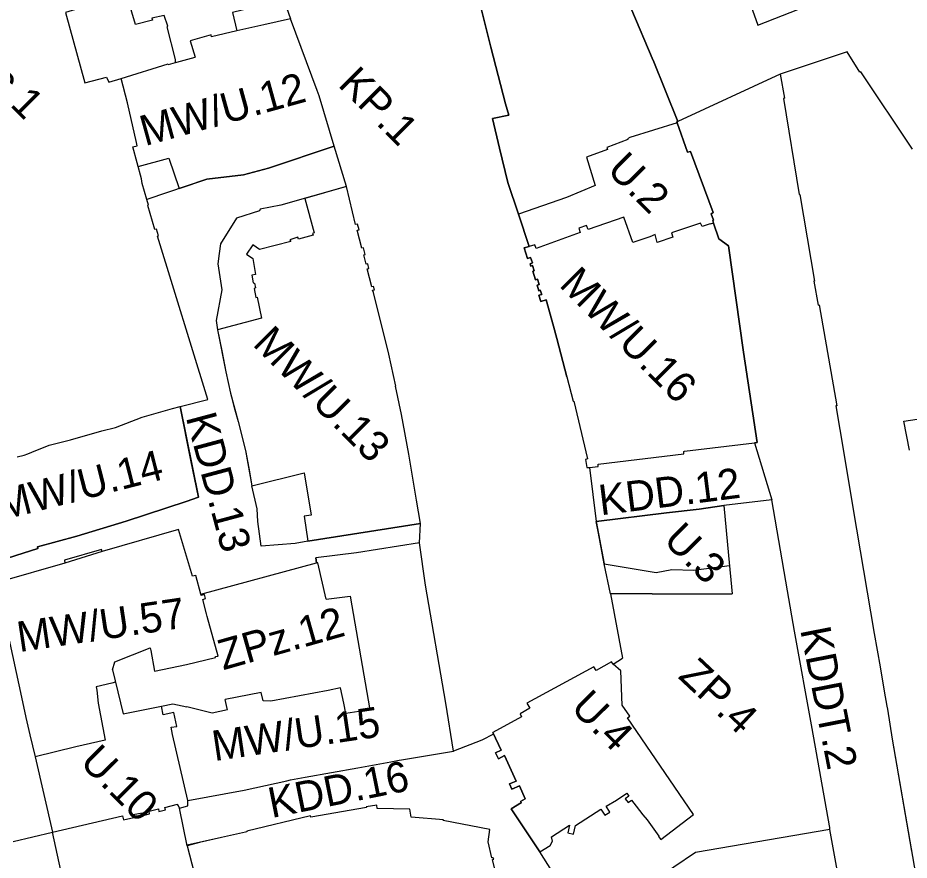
# Model space of a CAD drawing. Extents: x 7423835 to 7425280, y 5546086 to 5547600.
# Drawn here: x 7424593.5 to 7424769.7, y 5546646.4 to 5546812.9 of the extents above; entities that cross this region are included whole.
import ezdxf

# ---------------------------------------------------------------- set-up
doc = ezdxf.new("R2010")
doc.units = 0
for name, color, linetype in [('linie rozgraniczające', 7, 'Continuous'), ('nieprzekraczalne linie zabudowy', 7, 'Continuous'), ('obowiazujace linie zabudowy', 7, 'Continuous'), ('przeznaczenia terenów', 7, 'Continuous')]:
    doc.layers.add(name, color=color, linetype=linetype)

msp = doc.modelspace()

# ---------------------------------------------------------------- linework, layer by layer
at = {"layer": 'linie rozgraniczające'}
for p, q in [((7424744.2, 5546801.73), (7424723.96, 5546792.4)), ((7424658.44, 5546779.54), (7424656, 5546787.53)), ((7424739.1, 5546728.87), (7424742.53, 5546717.63)), ((7424706.52, 5546724.02), (7424707.81, 5546713.35)), ((7424673.09, 5546712.9), (7424650.85, 5546709.41)), ((7424672.9, 5546709.14), (7424673.09, 5546712.9)), ((7424710.67, 5546699.03), (7424713.01, 5546686.29)), ((7424718.86, 5546699.03), (7424734.7, 5546699.02)), ((7424711.18, 5546685.15), (7424713.01, 5546686.29)), ((7424626.99, 5546649.25), (7424625.45, 5546656.67)), ((7424696.68, 5546648.02), (7424691, 5546656.51)), ((7424592.61, 5546650.05), (7424600.35, 5546651.93)), ((7424600.28, 5546651.91), (7424602.25, 5546642.86)), ((7424758.3, 5546628.25), (7424754.02, 5546652.48)), ((7424706.02, 5546633.43), (7424696.68, 5546648.02))]:
    msp.add_line(p, q, dxfattribs=at)
for points in [[(7424707.32, 5546858.05), (7424711.92, 5546845.42), (7424716.09, 5546833.3), (7424721.67, 5546817.38), (7424714.67, 5546814.85), (7424719.05, 5546804.46), (7424719.1, 5546804.48), (7424723.96, 5546792.4), (7424723.75, 5546792.31), (7424723.82, 5546792.13), (7424725.89, 5546786.32), (7424726.44, 5546786.48), (7424730.93, 5546774.39), (7424730.57, 5546774.15), (7424730.99, 5546772.88), (7424730.86, 5546772.81), (7424730.99, 5546772.29), (7424732.04, 5546769.19), (7424733.94, 5546767.8), (7424736.9, 5546746.82), (7424739.64, 5546728.94), (7424739.1, 5546728.87)], [(7424751, 5546815.84), (7424727.03, 5546851.95), (7424725.66, 5546851.07), (7424739.75, 5546811.41), (7424751, 5546815.84)], [(7424643.66, 5546821.4), (7424646.21, 5546816.04), (7424647.41, 5546812.7)], [(7424702, 5546741.9), (7424700.04, 5546749.47), (7424699.37, 5546751.92), (7424697.94, 5546757.16), (7424696.87, 5546756.83), (7424696.49, 5546758.03), (7424697.06, 5546758.21), (7424696.74, 5546759.03), (7424696.48, 5546758.95), (7424696.14, 5546760.05), (7424696.54, 5546760.17), (7424696.22, 5546761.21), (7424695.8, 5546761.08), (7424695.27, 5546762.78), (7424695.58, 5546762.89), (7424695.23, 5546763.91), (7424694.91, 5546763.81), (7424694.75, 5546764.28), (7424695.2, 5546764.43), (7424694.83, 5546765.51), (7424694.26, 5546765.32), (7424693.6, 5546767.4), (7424694.54, 5546767.67), (7424692.46, 5546774.08), (7424690.38, 5546780.3), (7424688.7, 5546787.12), (7424687.32, 5546792.99), (7424690.57, 5546793.63), (7424689.87, 5546795.86), (7424686.98, 5546807.09), (7424683.36, 5546821.62)], [(7424647.41, 5546812.7), (7424647.41, 5546812.7), (7424642.11, 5546811.49), (7424636.8, 5546810.28), (7424631.79, 5546809.15), (7424631.69, 5546809.49), (7424627.56, 5546808.3), (7424628.58, 5546805.1)], [(7424656, 5546787.53), (7424653.03, 5546797.45), (7424652.66, 5546798.5), (7424647.41, 5546812.7)], [(7424770.35, 5546786.91), (7424760.14, 5546802.21), (7424759.95, 5546802.15), (7424757.39, 5546806.16), (7424744.2, 5546801.73), (7424745, 5546796.98), (7424744.83, 5546796.95), (7424747.95, 5546777.93), (7424748.07, 5546777.95), (7424750.99, 5546760.85), (7424750.82, 5546760.82), (7424751.7, 5546756.11), (7424751.86, 5546756.12), (7424755.35, 5546736.2), (7424755.21, 5546736.18), (7424756, 5546731.49), (7424759.29, 5546711.78), (7424762.74, 5546691.17), (7424763.95, 5546684.61), (7424764.73, 5546679.78), (7424765.23, 5546676.86), (7424765.39, 5546676.23), (7424766.34, 5546670.29), (7424771.49, 5546640.27)], [(7424613.91, 5546800.91), (7424623.22, 5546803.8), (7424623.27, 5546803.63), (7424624.67, 5546804.03), (7424624.91, 5546804.1), (7424628.58, 5546805.1)], [(7424625.59, 5546736.08), (7424631.08, 5546737.46), (7424621.12, 5546769.75), (7424621.3, 5546769.76), (7424620.9, 5546771.09), (7424620.56, 5546771.02), (7424619.19, 5546775.78), (7424619.31, 5546775.86), (7424618.99, 5546776.95), (7424618.07, 5546780.15), (7424617.92, 5546781.08), (7424616.24, 5546787.36), (7424617.08, 5546787.59), (7424616.94, 5546788.21), (7424615.16, 5546796.1), (7424613.91, 5546800.91), (7424613.91, 5546800.91)], [(7424723.82, 5546792.13), (7424714.48, 5546789.2)], [(7424714.48, 5546789.2), (7424714, 5546788.98), (7424714.05, 5546788.8), (7424709.93, 5546787.22), (7424710.05, 5546786.88), (7424705.87, 5546785.34), (7424707.63, 5546779.74), (7424701.94, 5546777.39), (7424692.46, 5546774.08)], [(7424656, 5546787.53), (7424643.06, 5546783.18), (7424638.14, 5546781.85), (7424630.83, 5546781), (7424618.99, 5546776.95)], [(7424658.44, 5546779.54), (7424645.46, 5546775.82), (7424641.39, 5546775.03), (7424641.24, 5546774.76), (7424636.75, 5546773.31), (7424633.58, 5546768.23), (7424633.3, 5546766.33), (7424633.01, 5546764.27), (7424633.81, 5546759.11), (7424632.73, 5546753.08), (7424632.99, 5546751.2), (7424634.64, 5546742.88), (7424635.52, 5546738.68), (7424637.05, 5546733.06), (7424638.51, 5546727.39), (7424639.78, 5546720.37)], [(7424673.09, 5546712.9), (7424672.33, 5546717.56), (7424670.76, 5546726.65), (7424669.36, 5546734.5), (7424668.12, 5546740.06), (7424668.22, 5546740.09), (7424666.82, 5546746.42), (7424663.77, 5546758.61), (7424663.63, 5546759.02), (7424664, 5546759.1), (7424663.83, 5546759.79), (7424663.47, 5546759.7), (7424662.54, 5546763.26), (7424662.88, 5546763.34), (7424662.65, 5546764.24), (7424662.33, 5546764.16), (7424661.88, 5546766.05), (7424662.16, 5546766.13), (7424661.81, 5546767.44), (7424661.52, 5546767.36), (7424660.55, 5546770.88), (7424660.94, 5546770.98), (7424660.65, 5546772.09), (7424660.23, 5546772.01), (7424658.44, 5546779.54)], [(7424730.99, 5546772.29), (7424730.36, 5546772.07), (7424730.33, 5546772.17), (7424728.77, 5546771.61), (7424728.45, 5546772.32), (7424722.68, 5546770.36), (7424722.93, 5546769.5), (7424719.89, 5546768.49), (7424719.47, 5546770.05), (7424718.41, 5546769.61), (7424715.03, 5546768.5), (7424713.25, 5546773.49), (7424706.2, 5546771.06), (7424705.91, 5546771.85), (7424704.4, 5546771.3), (7424704.64, 5546770.45), (7424695.95, 5546767.29), (7424695.69, 5546767.99), (7424694.54, 5546767.67)], [(7424702, 5546741.9), (7424703.25, 5546737.1), (7424703.4, 5546737.12), (7424706.11, 5546725.69), (7424705.67, 5546725.6), (7424705.99, 5546723.97), (7424706.52, 5546724.02), (7424708.21, 5546724.19), (7424708.18, 5546724.68), (7424725.16, 5546726.72), (7424725.11, 5546727.18), (7424725.25, 5546727.2), (7424739.1, 5546728.87)], [(7424593.38, 5546726.12), (7424594.73, 5546726.44), (7424595.51, 5546726.69), (7424596.28, 5546727.03), (7424599.71, 5546728.44), (7424603.9, 5546729.49), (7424610.1, 5546731.22), (7424612.8, 5546731.92), (7424618.1, 5546733.93), (7424618.56, 5546734.06), (7424624.08, 5546735.64), (7424625.59, 5546736.08), (7424629.2, 5546718.11), (7424626.77, 5546717.3), (7424614.94, 5546713.4), (7424605.17, 5546710.42), (7424597.4, 5546708.32), (7424597.47, 5546708.02), (7424588.52, 5546705.15)], [(7424769.71, 5546727.43), (7424768.63, 5546733.16), (7424772.59, 5546733.72)], [(7424650.85, 5546709.41), (7424648.29, 5546708.97), (7424641.62, 5546708.44), (7424640.96, 5546713.32), (7424640.8, 5546715.86), (7424639.78, 5546720.37)], [(7424707.81, 5546713.35), (7424721.68, 5546715.07), (7424728.18, 5546715.79), (7424733.05, 5546716.46)], [(7424754.02, 5546652.48), (7424753.96, 5546652.84), (7424753.9, 5546653.2), (7424750.47, 5546672.42), (7424747.04, 5546691.63), (7424745.65, 5546699.61), (7424742.53, 5546717.63), (7424733.05, 5546716.46)], [(7424733.05, 5546716.46), (7424733.97, 5546706.6), (7424734.7, 5546699.02)], [(7424718.86, 5546699.03), (7424710.67, 5546699.03), (7424709.38, 5546704.99), (7424708.25, 5546710.99), (7424707.81, 5546713.35)], [(7424629.67, 5546698.97), (7424628.68, 5546702.66), (7424628.03, 5546702.52), (7424625.27, 5546711.72), (7424610.16, 5546707.38), (7424610.03, 5546707.78), (7424602.7, 5546705.68), (7424602.82, 5546705.09), (7424602.82, 5546705.09)], [(7424591.23, 5546692.64), (7424594.43, 5546677.7), (7424595.11, 5546674.57), (7424595.9, 5546671.13), (7424596.9, 5546666.81), (7424600.35, 5546651.93), (7424614.17, 5546655.13), (7424614.38, 5546654.38), (7424616.4, 5546654.84), (7424616.27, 5546655.4), (7424618.1, 5546655.76), (7424618.23, 5546655.25), (7424619.56, 5546655.56), (7424619.43, 5546656.08), (7424621.28, 5546656.52), (7424621.4, 5546655.99), (7424622.7, 5546656.37), (7424622.59, 5546656.82), (7424625.04, 5546657.46), (7424625.07, 5546657.27), (7424625.12, 5546657.26), (7424625.45, 5546656.67), (7424627.08, 5546657.11), (7424627.12, 5546658.15), (7424638.25, 5546660.23), (7424646.64, 5546662.1), (7424647.37, 5546662.27), (7424650.31, 5546662.79), (7424660.7, 5546664.64), (7424667.21, 5546665.81), (7424668.9, 5546666.16), (7424669.35, 5546666.23), (7424674.48, 5546667.07), (7424679.61, 5546667.91), (7424678.08, 5546677.4), (7424674.08, 5546700.75), (7424672.9, 5546709.14), (7424660.46, 5546707.14), (7424652.38, 5546706.14)], [(7424629.67, 5546698.97), (7424652.55, 5546705.19), (7424652.38, 5546706.14)], [(7424602.82, 5546705.09), (7424589.91, 5546701.38)], [(7424654.45, 5546698), (7424652.83, 5546705.14), (7424652.55, 5546705.19)], [(7424633.09, 5546686.72), (7424630.95, 5546694.57), (7424630.82, 5546695.1), (7424630.1, 5546697.91), (7424630.6, 5546698.12), (7424630.37, 5546698.88), (7424629.73, 5546698.73), (7424629.67, 5546698.97)], [(7424654.45, 5546698), (7424659.17, 5546698.56), (7424663.07, 5546676.13)], [(7424612.19, 5546683.99), (7424612.67, 5546685.62), (7424619.65, 5546688.38)], [(7424619.65, 5546688.38), (7424619.76, 5546687.82), (7424620.54, 5546683.74), (7424626.84, 5546685.09), (7424632.58, 5546686.47), (7424632.55, 5546686.62), (7424633.09, 5546686.72)], [(7424712.71, 5546683.83), (7424711.18, 5546685.15), (7424710.87, 5546685.61), (7424707.82, 5546683.86), (7424707.38, 5546684.61), (7424694.13, 5546677.39), (7424694.7, 5546676.4), (7424692.79, 5546675.33), (7424693.04, 5546674.74), (7424687.39, 5546671.62)], [(7424612.19, 5546683.99), (7424614.35, 5546675.34), (7424621.92, 5546676.85), (7424624.16, 5546677.3), (7424626.91, 5546676.7)], [(7424696.68, 5546648.02), (7424698.72, 5546649.31), (7424699.18, 5546650.15), (7424698.98, 5546651.02), (7424702.54, 5546653.28), (7424702.24, 5546651.76), (7424703.35, 5546651.53), (7424703.71, 5546653.27), (7424708.75, 5546656.47), (7424709.5, 5546655.27), (7424710.5, 5546655.9), (7424709.76, 5546657.09), (7424711.81, 5546658.27), (7424713.89, 5546659.66), (7424714.28, 5546659.02), (7424713.57, 5546658.52), (7424714.15, 5546657.8), (7424714.8, 5546658.26), (7424715.73, 5546657.05), (7424717.03, 5546655.34), (7424717.89, 5546654.36), (7424720.21, 5546651.15), (7424720.16, 5546651.08), (7424720.58, 5546650.46), (7424727.03, 5546655.39), (7424713.97, 5546674.52), (7424714.49, 5546674.83), (7424712.94, 5546677.03), (7424712.71, 5546683.83)], [(7424612.79, 5546681.57), (7424612.11, 5546681.37), (7424608.99, 5546680.63), (7424609.11, 5546679.97), (7424609.35, 5546677.42), (7424610.77, 5546670.09), (7424604.95, 5546668.79), (7424596.9, 5546666.81)], [(7424663.07, 5546676.13), (7424662.64, 5546676.06), (7424658.36, 5546675.4), (7424657.97, 5546677.41), (7424657.29, 5546680.48), (7424654.84, 5546679.91), (7424643.53, 5546677.81), (7424642, 5546677.85), (7424641.58, 5546679.51), (7424634.5, 5546678.16)], [(7424634.94, 5546676.09), (7424634.89, 5546676.35), (7424634.5, 5546678.16)], [(7424627.12, 5546658.15), (7424624.07, 5546671.24), (7424623.81, 5546672.66), (7424624.93, 5546672.83), (7424624.37, 5546675.57), (7424622.25, 5546675.14), (7424621.92, 5546676.85)], [(7424634.94, 5546676.09), (7424631.89, 5546675.45), (7424626.91, 5546676.7)], [(7424687.54, 5546671.3), (7424685.18, 5546670.09), (7424679.61, 5546667.91)], [(7424691, 5546656.51), (7424693.02, 5546657.76), (7424692.88, 5546657.99), (7424693.79, 5546658.54), (7424692.63, 5546661.07), (7424691.13, 5546660.43), (7424690.67, 5546661.47), (7424692.01, 5546662.03), (7424689.67, 5546667.05), (7424688.48, 5546666.43), (7424687.94, 5546667.59), (7424689.02, 5546668.14), (7424687.39, 5546671.62)], [(7424689.87, 5546635.82), (7424687.29, 5546646.51), (7424687.56, 5546646.57), (7424687.47, 5546646.87), (7424687.22, 5546646.82), (7424686.45, 5546650.01), (7424686.77, 5546652.42), (7424677.6, 5546654.2), (7424677.63, 5546654.36), (7424671.22, 5546654.91), (7424670.97, 5546656.48), (7424664.53, 5546656.62), (7424664.44, 5546657.27), (7424662.37, 5546656.94), (7424662.39, 5546656.79), (7424651.42, 5546654.92), (7424651.33, 5546655.18), (7424638.75, 5546652.11), (7424638.77, 5546652.01), (7424638.51, 5546651.93), (7424633.79, 5546650.84), (7424629.42, 5546649.87), (7424626.99, 5546649.25), (7424631.53, 5546631.4)], [(7424754.02, 5546652.48), (7424727.46, 5546647.88), (7424706.02, 5546633.43)]]:
    msp.add_lwpolyline(points, dxfattribs=at)
at = {"layer": 'nieprzekraczalne linie zabudowy'}
msp.add_line((7424610.16, 5546707.38), (7424602.82, 5546705.09), dxfattribs=at)
for points in [[(7424617.27, 5546783.51), (7424623.35, 5546785.14), (7424625.41, 5546779.14)], [(7424722.79, 5546703.86), (7424727.07, 5546703.7), (7424734.16, 5546704.63)]]:
    msp.add_lwpolyline(points, dxfattribs=at)
at = {"layer": 'obowiazujace linie zabudowy'}
for p, q in [((7424658.44, 5546779.54), (7424650.21, 5546777.18)), ((7424627.73, 5546725.42), (7424625.59, 5546736.08)), ((7424650.85, 5546709.41), (7424673.09, 5546712.9)), ((7424691, 5546656.51), (7424696.68, 5546648.02))]:
    msp.add_line(p, q, dxfattribs=at)
for points in [[(7424739.1, 5546728.87), (7424739.64, 5546728.94), (7424736.9, 5546746.82), (7424733.94, 5546767.8), (7424732.04, 5546769.19), (7424730.99, 5546772.29), (7424730.86, 5546772.81), (7424730.99, 5546772.88), (7424730.57, 5546774.15), (7424730.93, 5546774.39), (7424726.44, 5546786.48), (7424725.89, 5546786.32), (7424723.82, 5546792.13), (7424723.75, 5546792.31), (7424723.96, 5546792.4), (7424719.1, 5546804.48), (7424719.05, 5546804.46), (7424714.67, 5546814.85), (7424721.67, 5546817.38), (7424716.09, 5546833.3), (7424711.92, 5546845.42), (7424707.32, 5546858.05)], [(7424617.07, 5546820.29), (7424614.34, 5546819.62), (7424606.95, 5546817.32), (7424607.56, 5546815.34), (7424602.92, 5546813.96), (7424606.74, 5546800), (7424611.02, 5546801.16), (7424611.48, 5546800.15), (7424613.91, 5546800.91)], [(7424624.67, 5546804.03), (7424624.69, 5546804.66), (7424623.01, 5546811.13), (7424623.17, 5546811.2), (7424622.42, 5546813.32), (7424619.96, 5546812.8), (7424620.09, 5546812.4), (7424616.79, 5546811.55), (7424615.3, 5546816.47), (7424617.95, 5546817.15), (7424617.07, 5546820.29)], [(7424683.36, 5546821.62), (7424686.98, 5546807.09), (7424689.87, 5546795.86), (7424690.57, 5546793.63), (7424687.32, 5546792.99), (7424688.7, 5546787.12), (7424690.38, 5546780.3), (7424692.46, 5546774.08), (7424694.54, 5546767.67), (7424693.6, 5546767.4), (7424694.26, 5546765.32), (7424694.83, 5546765.51), (7424695.2, 5546764.43), (7424694.75, 5546764.28), (7424694.91, 5546763.81), (7424695.23, 5546763.91), (7424695.58, 5546762.89), (7424695.27, 5546762.78), (7424695.8, 5546761.08), (7424696.22, 5546761.21), (7424696.54, 5546760.17), (7424696.14, 5546760.05), (7424696.48, 5546758.95), (7424696.74, 5546759.03), (7424697.06, 5546758.21), (7424696.49, 5546758.03), (7424696.87, 5546756.83), (7424697.94, 5546757.16), (7424699.37, 5546751.92), (7424700.04, 5546749.47), (7424702, 5546741.9)], [(7424646.04, 5546816.39), (7424635.93, 5546813.96), (7424636.8, 5546810.28)], [(7424656, 5546787.53), (7424653.03, 5546797.45), (7424652.66, 5546798.5), (7424647.41, 5546812.7)], [(7424770.35, 5546786.91), (7424760.14, 5546802.21), (7424759.95, 5546802.15), (7424757.39, 5546806.16), (7424744.2, 5546801.73), (7424745, 5546796.98), (7424744.83, 5546796.95), (7424747.95, 5546777.93), (7424748.07, 5546777.95), (7424750.99, 5546760.85), (7424750.82, 5546760.82), (7424751.7, 5546756.11), (7424751.86, 5546756.12), (7424755.35, 5546736.2), (7424755.21, 5546736.18), (7424756, 5546731.49), (7424759.29, 5546711.78), (7424762.74, 5546691.17), (7424763.95, 5546684.61), (7424764.73, 5546679.78), (7424765.23, 5546676.86), (7424765.39, 5546676.23), (7424766.34, 5546670.29), (7424770.14, 5546648.15)], [(7424625.41, 5546779.14), (7424630.83, 5546781), (7424638.14, 5546781.85), (7424643.06, 5546783.18), (7424656, 5546787.53)], [(7424673.09, 5546712.9), (7424672.33, 5546717.56), (7424670.76, 5546726.65), (7424669.36, 5546734.5), (7424668.12, 5546740.06), (7424668.22, 5546740.09), (7424666.82, 5546746.42), (7424663.77, 5546758.61), (7424663.63, 5546759.02), (7424664, 5546759.1), (7424663.83, 5546759.79), (7424663.47, 5546759.7), (7424662.54, 5546763.26), (7424662.88, 5546763.34), (7424662.65, 5546764.24), (7424662.33, 5546764.16), (7424661.88, 5546766.05), (7424662.16, 5546766.13), (7424661.81, 5546767.44), (7424661.52, 5546767.36), (7424660.55, 5546770.88), (7424660.94, 5546770.98), (7424660.65, 5546772.09), (7424660.23, 5546772.01), (7424658.44, 5546779.54)], [(7424650.21, 5546777.18), (7424652.06, 5546770.39), (7424651.77, 5546770.28), (7424651.88, 5546769.93), (7424648.95, 5546769.15), (7424648.83, 5546769.53), (7424647.29, 5546769.03), (7424647.43, 5546768.64), (7424641.25, 5546767.09), (7424639.95, 5546768.02), (7424638.71, 5546766.18), (7424639.96, 5546765.32), (7424640.48, 5546762.17), (7424639.73, 5546762.02), (7424640, 5546760.47), (7424640.28, 5546760.45), (7424640.47, 5546759.51), (7424640.2, 5546759.4), (7424640.53, 5546757.57), (7424640.83, 5546757.64), (7424641.69, 5546753.52), (7424632.99, 5546751.2)], [(7424632.99, 5546751.2), (7424633.82, 5546747.04), (7424634.64, 5546742.88), (7424635.52, 5546738.68), (7424636.29, 5546735.87), (7424637.05, 5546733.06), (7424637.78, 5546730.23), (7424638.51, 5546727.39), (7424639.15, 5546723.88), (7424639.78, 5546720.37)], [(7424702, 5546741.9), (7424703.25, 5546737.1), (7424703.4, 5546737.12), (7424706.11, 5546725.69), (7424705.67, 5546725.6), (7424705.99, 5546723.97), (7424706.52, 5546724.02), (7424708.21, 5546724.19), (7424708.18, 5546724.68), (7424725.16, 5546726.72), (7424725.11, 5546727.18), (7424725.25, 5546727.2), (7424739.1, 5546728.87)], [(7424626.77, 5546717.3), (7424629.2, 5546718.11), (7424627.73, 5546725.42)], [(7424583.6, 5546722.64), (7424584.37, 5546718.9), (7424588.52, 5546705.15), (7424597.47, 5546708.02), (7424597.4, 5546708.32), (7424605.17, 5546710.42), (7424614.94, 5546713.4), (7424626.77, 5546717.3)], [(7424639.78, 5546720.37), (7424650.08, 5546722.95), (7424651.5, 5546714.55), (7424650.12, 5546714.35), (7424650.85, 5546709.41)], [(7424733.05, 5546716.46), (7424728.18, 5546715.79), (7424721.68, 5546715.07), (7424707.81, 5546713.35), (7424709.38, 5546704.99)], [(7424629.67, 5546698.97), (7424628.68, 5546702.66), (7424628.03, 5546702.52), (7424625.27, 5546711.72), (7424610.16, 5546707.38)], [(7424591.23, 5546692.64), (7424594.43, 5546677.7), (7424595.11, 5546674.57), (7424595.9, 5546671.13), (7424596.9, 5546666.81), (7424600.35, 5546651.93), (7424614.17, 5546655.13), (7424614.38, 5546654.38), (7424616.4, 5546654.84), (7424616.27, 5546655.4), (7424618.1, 5546655.76), (7424618.23, 5546655.25), (7424619.56, 5546655.56), (7424619.43, 5546656.08), (7424621.28, 5546656.52), (7424621.4, 5546655.99), (7424622.7, 5546656.37), (7424622.59, 5546656.82), (7424625.04, 5546657.46), (7424625.07, 5546657.27), (7424625.12, 5546657.26), (7424625.45, 5546656.67), (7424627.08, 5546657.11), (7424627.12, 5546658.15), (7424638.25, 5546660.23), (7424646.64, 5546662.1), (7424647.37, 5546662.27), (7424650.31, 5546662.79), (7424660.7, 5546664.64), (7424667.21, 5546665.81), (7424668.9, 5546666.16), (7424669.35, 5546666.23), (7424674.48, 5546667.07), (7424679.61, 5546667.91), (7424678.08, 5546677.4), (7424674.08, 5546700.75), (7424672.9, 5546709.14), (7424660.46, 5546707.14), (7424652.38, 5546706.14)], [(7424652.38, 5546706.14), (7424652.55, 5546705.19)], [(7424602.82, 5546705.09), (7424589.91, 5546701.38)], [(7424602.82, 5546705.09), (7424602.82, 5546705.09)], [(7424709.38, 5546704.99), (7424719.69, 5546703.22), (7424722.79, 5546703.86)], [(7424710.87, 5546685.61), (7424707.82, 5546683.86), (7424707.38, 5546684.61), (7424694.13, 5546677.39), (7424694.7, 5546676.4), (7424692.79, 5546675.33), (7424693.04, 5546674.74), (7424687.39, 5546671.62)], [(7424687.39, 5546671.62), (7424689.02, 5546668.14), (7424687.94, 5546667.59), (7424688.48, 5546666.43), (7424689.67, 5546667.05), (7424692.01, 5546662.03), (7424690.67, 5546661.47), (7424691.13, 5546660.43), (7424692.63, 5546661.07), (7424693.79, 5546658.54), (7424692.88, 5546657.99), (7424693.02, 5546657.76), (7424691, 5546656.51)], [(7424689.87, 5546635.82), (7424687.29, 5546646.51), (7424687.56, 5546646.57), (7424687.47, 5546646.87), (7424687.22, 5546646.82), (7424686.45, 5546650.01), (7424686.77, 5546652.42), (7424677.6, 5546654.2), (7424677.63, 5546654.36), (7424671.22, 5546654.91), (7424670.97, 5546656.48), (7424664.53, 5546656.62), (7424664.44, 5546657.27), (7424662.37, 5546656.94), (7424662.39, 5546656.79), (7424651.42, 5546654.92), (7424651.33, 5546655.18), (7424638.75, 5546652.11), (7424638.77, 5546652.01), (7424638.51, 5546651.93), (7424633.79, 5546650.84), (7424626.97, 5546649.33)], [(7424626.99, 5546649.25), (7424629.26, 5546640.33), (7424631.53, 5546631.4), (7424632.02, 5546629.52), (7424632.5, 5546627.64), (7424634.32, 5546621.51)]]:
    msp.add_lwpolyline(points, dxfattribs=at)

# ---------------------------------------------------------------- texts
at = {"layer": 'przeznaczenia terenów'}
for s, rotation, p in [('ZPc.1', 314.9764, (7424580.11, 5546807.25)), ('KP.1', 314.9764, (7424656.57, 5546799.51)), ('MW/U.12', 15.4259, (7424618.62, 5546787.51)), ('U.2', 314.9764, (7424709.71, 5546782.6)), ('MW/U.16', 314.9764, (7424700.3, 5546759.97)), ('MW/U.13', 314.9764, (7424639.72, 5546748.27)), ('KDD.13', 285.0128, (7424626.68, 5546733.96)), ('MW/U.14', 14.3097, (7424590.23, 5546713.5)), ('KDD.12', 7.1674, (7424708.7, 5546714.54)), ('U.3', 314.9764, (7424720.86, 5546709.42)), ('MW/U.57', 8.4246, (7424593.8, 5546687.51)), ('ZPz.12', 15.8139, (7424634.07, 5546683.91)), ('KDDT.2', 281.1189, (7424748.12, 5546691.95)), ('ZP.4', 316.7216, (7424723.82, 5546682.53)), ('U.4', 314.9764, (7424702.55, 5546676.32)), ('MW/U.15', 8.4246, (7424632.35, 5546665.96)), ('U.10', 314.9764, (7424605.53, 5546665.54)), ('KDD.16', 11.3615, (7424643.66, 5546654.7))]:
    msp.add_text(s, height=6, rotation=rotation, dxfattribs=at).set_placement(p)

doc.saveas('drawing.dxf')
